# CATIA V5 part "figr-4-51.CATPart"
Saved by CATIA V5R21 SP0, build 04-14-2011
Part number: Part1
Material "Aluminium": density 2710 kg/m3, Young's modulus 7e+10 Pa, Poisson ratio 0.346, thermal expansion 2.36e-05 1/K
Bounding box of the stored display mesh (mm): x -69.981 to 69.981, y -240 to 0, z -69.908 to 69.908
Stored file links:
  D:\CATIA V5R21 E-RESOURCES\CATIA-V5R21\catia-v5r21-prt\c04-catia-v5r20-prt\catia-v5r21-figr-4-51.CATPart
  C:\Program Files\Dassault Systemes\B21\win_b64\startup\materials\Catalog.CATMaterial
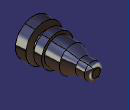
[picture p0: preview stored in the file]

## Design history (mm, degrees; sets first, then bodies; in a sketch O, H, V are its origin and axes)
Body1 (main body), material "Steel"
  Sketch1 on yz-plane, origin (0, 0, 0), H (0, 1, 0), V (0, 0, 1)
    line L1 (0, 0) -> (0, 15.359)
    arc A1 centre (-15.359, 15.359) radius 15.359 from (0, 15.359) to (-15.359, 30.718) ccw
    point P2 (-15.359, 15.359)
    line L2 (-15.359, 30.718) -> (-49.6877, 30.718)
    line L3 (-49.6877, 30.718) -> (-91.8922, 49.6007)
    line L4 (-91.8922, 49.6007) -> (-149.3038, 49.6007)
    line L5 (-149.3038, 49.6007) -> (-149.3038, 60)
    line L6 (-149.3038, 60) -> (-180, 60)
    line L7 (-180, 60) -> (-180, 38.9967)
    line L8 (-180, 38.9967) -> (-200, 40)
    line L9 (-200, 40) -> (-200, 70)
    line L10 (-200, 70) -> (-240, 70)
    line L11 (-240, 70) -> (-240, 0)
    line L12 (-240, 0) -> (0, 0)
    axis line L13 (-300, 0) -> (50, 0)
    vertical: L1 V, L5 V, L7 V, L9 V, L11 V
    tangency: A1 L1, L2 A1, L8 A1, L12 A1, L13 A1
    coincidence: L3 P2
    horizontal: L4 H, L6 H, L10 H, L2 H
    fix: L12
  Shaft1: profile Sketch1, axis Sketch1.H, angle 360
